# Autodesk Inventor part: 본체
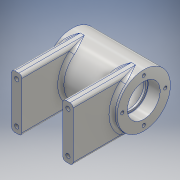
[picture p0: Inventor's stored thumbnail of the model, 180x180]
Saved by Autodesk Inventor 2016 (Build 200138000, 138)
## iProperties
Created: 2020-07
Part Number: 본체
Material: 알루미늄 6061
Document SubType Name: Modeling
Designer: user
Density: 2.7 g/cm^3
Appearance: 알루미늄 - 평지
Author: user
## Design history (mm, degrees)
sketch "스케치8"
  geometry: L1 (0, 26)-(-64, 26); L2 (-64, 26)-(-64, -26); L3 (-64, -26)-(0, -26); A1 r 26 centre (0, 0) between (0, 26) and (0, -26); 2 further points
  constraints: 6 end point, 2 coincident, 2 point on circle, 1 centre point, 1 horizontal, 1 perpendicular, 1 tangent, 1 vertical alignment, 2 other
  dimensions: "d27" = 52 diameter of A1; "d28" = 64 distance of L1.start L1.end; "d29" = 52 distance of L1.end L2.end; "d30" = 64 distance of L2.end L3.end
extrude "돌출2" new body sketch "스케치8" distance "d31" = 10; taper "d32" = 0 deg
sketch "스케치9"
  geometry: A1 r 26 centre (0, 0) between (0, 26) and (0, -26) reference; 2 further points
  constraints: 1 coincident, 1 vertical alignment, 2 other
extrude "돌출3" join sketch "스케치9" distance "d33" = 5; taper "d34" = 0 deg
sketch "스케치10"
  geometry: C1 r 26 at (0, 0); 1 further point
  constraints: 1 centre point, 1 coincident
extrude "돌출4" join sketch "스케치10" distance "d35" = 50; taper "d36" = 0 deg
sketch "스케치11"
  geometry: L1 (26, -64)-(26, 0) reference; L2 (26, 0)-(26, -64); L3 (26, -64)-(-26, -64); L4 (-26, -64)-(-26, 0); A1 r 26 centre (0, 0) between (-26, 0) and (26, 0); 1 further point
  constraints: 6 end point, 2 point on circle, 1 centre point, 1 coincident, 1 collinear, 1 perpendicular
  dimensions: "d40" = 64 distance of L1.end L1.start (derived); "d41" = 52 distance of L1.start L3.end; "d42" = 64 distance of L3.end L4.end (derived)
extrude "돌출5" join sketch "스케치11" distance "d43" = 10; taper "d44" = 0 deg
sketch "스케치12"
  geometry: C1 r 26 at (0, 0); 1 further point
  constraints: 1 centre point, 1 coincident
extrude "돌출6" join sketch "스케치12" distance "d45" = 15; taper "d46" = 0 deg
sketch "스케치13"
  geometry: L1 (-5, 26)-(-5, -26) reference; L2 (-5, 0)-(65, 0); L3 (-5, 0)-(7, 0); L4 (7, 0)-(7, 16); L5 (7, 16)-(-5, 16); L6 (-5, 16)-(-5, 0); L7 (7, 0)-(9, 0); L8 (9, 0)-(9, 14); L9 (9, 14)-(7, 14); L10 (7, 14)-(7, 0); L11 (9, 0)-(51.31, 0); L12 (51.31, 0)-(53, 0); L13 (53, 0)-(65, 0); L14 (9, 0)-(51, 0); L15 (51, 0)-(51, 21); L16 (51, 21)-(9, 21); L17 (9, 21)-(9, 0); L18 (51, 0)-(53, 0); L19 (53, 0)-(53, 14); L20 (53, 14)-(51, 14); L21 (51, 14)-(51, 0); L22 (50, -26)-(50, 0) reference; L23 (65, -26)-(65, 26) reference; L24 (50, 0)-(65, 0); L25 (53, 0)-(65, 0); L26 (65, 0)-(65, 16); L27 (65, 16)-(53, 16); L28 (53, 16)-(53, 0); 1 further point
  constraints: 50 end point, 10 parallel, 9 horizontal, 5 perpendicular, 1 midpoint, 1 point on line
  dimensions: "d48" = 32 diameter of L5 L2; "d49" = 28 diameter of L9 L2; "d56" = 2 distance between parallel lines of L8 L10; "d57" = 12 distance between parallel lines of L1 L4; "d58" = 12 distance between parallel lines of L26 L19; "d59" = 42 distance between parallel lines of L17 L15; "d73" = 42 diameter of L16 L2
revolve "회전2" sketch "스케치13" stored, may be unused: angle "d60" = 90 deg
sketch "스케치17"
  geometry: A1 r 21 centre (0, 0) between (0, 21) and (21, 0); 3 further points
  constraints: 4 point on circle, 1 centre point, 1 coincident
  dimensions: "d65" = 42 diameter of A1
hole "구멍1" sketch "스케치17" at (0, 21), (21, 0), (0, -21), (-21, 0) diameter "d66" = 3.242; stored, may be unused: countersink angle "d70" = 90 deg, drill point angle "d72" = 118 deg; dims "d67" = 8, "d68" = 4, "d69" = 2, "d71" = 10
fillet "모깎기1" dims "d77" = 3
sketch "스케치22"
  geometry: 1 further point
sketch "스케치23"
  geometry: 8 further points
  constraints: 2 coincident
hole "구멍2" sketch "스케치23" at (0, 21), (-21, 0), (21, 0), (0, -21) diameter "d79" = 3.242; stored, may be unused: countersink angle "d83" = 90 deg, drill point angle "d85" = 118 deg; dims "d80" = 8, "d81" = 4, "d82" = 2, "d84" = 10
sketch "스케치24"
  geometry: L1 (-50, 46)-(-50, 0) reference; L2 (-45, 3.621)-(-45, 0.379) reference; L3 (5, 0.379)-(5, 3.621) reference; 5 further points
hole "구멍3" sketch "스케치24" at (-45, 43), (-45, 3), (5, 3), (5, 43) diameter "d93" = 4.134; stored, may be unused: countersink angle "d97" = 90 deg, drill point angle "d99" = 118 deg; dims "d94" = 10, "d95" = 4, "d96" = 2, "d98" = 10
sketch "스케치25"
  geometry: L1 (5, 1.621)-(5, -1.621) reference; C1 r 5 at (-30, 0); 1 further point
  constraints: 1 centre point
  dimensions: "d101" = 10 diameter of C1
extrude "돌출8" join sketch "스케치25" distance "d102" = 29; taper "d103" = 0 deg
sketch "스케치26"
  geometry: C1 r 14 at (0, 0); 1 further point
  constraints: 1 centre point, 1 coincident
extrude "돌출9" cut sketch "스케치26" distance "d104" = 100; taper "d105" = 0 deg
node "스케치27"
sketch "스케치28"
  geometry: C1 r 21 at (0, 0); 1 further point
  constraints: 1 centre point, 1 coincident
  dimensions: "d106" = 42 diameter of C1
extrude "돌출10" cut sketch "스케치28" distance "d107" = 42; taper "d108" = 0 deg
sketch "스케치29"
  geometry: 2 further points
hole "구멍4" sketch "스케치29" at (0, 0) diameter "d109" = 5.188; stored, may be unused: countersink angle "d113" = 90 deg, drill point angle "d115" = 118 deg; dims "d110" = 16, "d111" = 4, "d112" = 2, "d114" = 20
fillet "모깎기2" dims "d116" = 0.3
sketch "스케치30"
  geometry: 1 further point
fillet "모깎기3" dims "d119" = 2
fillet "모깎기4" dims "d120" = 3
node "솔리드2"
